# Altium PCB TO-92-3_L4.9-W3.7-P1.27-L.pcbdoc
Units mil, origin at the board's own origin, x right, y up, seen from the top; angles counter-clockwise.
Board outline 697.96 x 667.64 mil, 2 copper layers (Top Layer, Bottom Layer), stack 0 mil thick; 1 components, 0 nets, 3 pads, 0 vias.
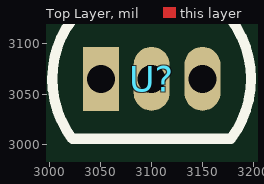
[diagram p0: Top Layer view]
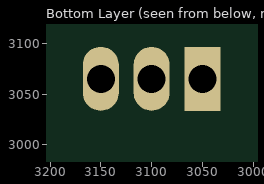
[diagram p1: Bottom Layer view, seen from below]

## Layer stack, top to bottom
Top Layer: signal copper (thickness not stored)
Bottom Layer: signal copper (thickness not stored)

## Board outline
3447.96,2750 2750,2750 2750,3417.64 3447.96,3417.64

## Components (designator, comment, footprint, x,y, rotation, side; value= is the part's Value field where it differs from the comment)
U? "" TO-92-3_L4.9-W3.7-P1.27-L 3100.16,3065 r0 top

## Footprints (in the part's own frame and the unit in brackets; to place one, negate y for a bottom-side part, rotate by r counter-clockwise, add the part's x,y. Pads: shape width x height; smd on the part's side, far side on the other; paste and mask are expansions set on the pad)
TO-92-3_L4.9-W3.7-P1.27-L [mm]
  rect 0.9x1.6 hole 0.7: 1(-1.27,0)
  oval 0.9x1.6 hole 0.7: 2(0,0) 3(1.27,0)
  silkscreen extent -2.48,-1.5 2.48,2.48

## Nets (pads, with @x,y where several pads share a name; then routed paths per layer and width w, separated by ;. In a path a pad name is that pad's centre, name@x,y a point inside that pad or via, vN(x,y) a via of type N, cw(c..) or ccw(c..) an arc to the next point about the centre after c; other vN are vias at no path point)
pads on no net: U?.1 U?.2 U?.3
